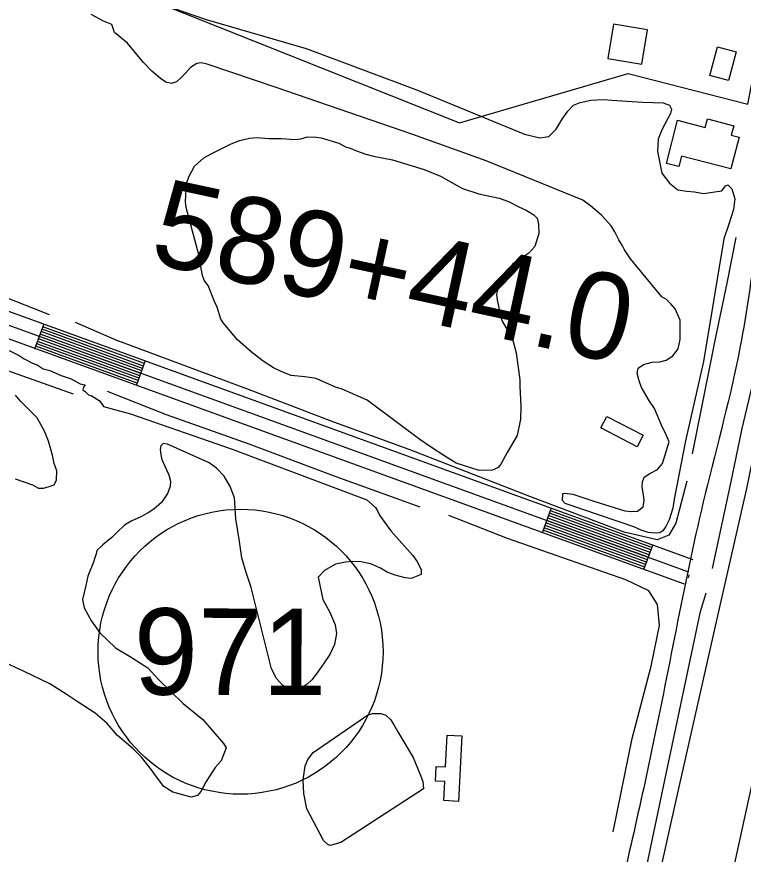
# Model space of a CAD drawing. Extents: x 3161564 to 3199464, y 849354 to 874788.
# Drawn here: x 3175202 to 3176044, y 870482 to 871452 of the extents above; entities that cross this region are included whole.
import ezdxf

# ---------------------------------------------------------------- set-up
doc = ezdxf.new("R2010")
doc.units = 0
for name, color, linetype in [('V-BLDG-OTLN', 7, 'Continuous'), ('V-LEVE-TOET', 7, 'Continuous'), ('V-ROAD-CNTR', 7, 'Continuous'), ('V-ROAD-IDEN', 7, 'Continuous'), ('V-SITE-VEGE', 7, 'Continuous'), ('V-SURV-IDEN', 7, 'Continuous'), ('V-SURV-LINE', 7, 'Continuous'), ('V-TOPO-SHOR', 7, 'Continuous')]:
    doc.layers.add(name, color=color, linetype=linetype)

msp = doc.modelspace()

# ---------------------------------------------------------------- linework, layer by layer
at = {"layer": 'V-BLDG-OTLN'}
for points in [[(3175886.83, 871403.4), (3175926.29, 871396.84), (3175932.85, 871436.3), (3175893.39, 871442.86)], [(3176026.57, 871377.88), (3176004.84, 871383.71), (3176013.71, 871416.78), (3176035.44, 871410.95)], [(3176029.37, 871275.43), (3175972.1, 871290.22), (3175968.99, 871278.16), (3175954.66, 871281.86), (3175967.55, 871331.8), (3175999.57, 871323.54), (3176002.08, 871333.25), (3176032.57, 871325.38), (3176029.78, 871314.53), (3176038.85, 871312.19)], [(3175927.8, 870967.13), (3175920.9, 870953.7), (3175878.57, 870975.46), (3175885.48, 870988.89)], [(3175713.82, 870543.08), (3175696.98, 870543.92), (3175698.1, 870566.1), (3175687.38, 870566.64), (3175688.24, 870583.62), (3175698.94, 870583.09), (3175700.79, 870619.84), (3175717.64, 870618.99)]]:
    msp.add_lwpolyline(points, close=True, dxfattribs=at)
at = {"layer": 'V-LEVE-TOET'}
msp.add_lwpolyline([(3175669.74, 869514.51), (3175708.2, 869561.86), (3175732.37, 869595.77), (3175748.33, 869623.04), (3175762.06, 869648.88), (3175775.26, 869685.57), (3175784.89, 869728.04), (3175832.2, 869934.29), (3175892.9, 870206.66), (3175926.27, 870366.31), (3175967.07, 870549.35), (3176018.86, 870778.5), (3176047.93, 870905.33), (3176080.45, 871065.53), (3176105.08, 871234.71), (3176159.34, 871580.12), (3176184.86, 871793.43), (3176216.77, 872030.74), (3176255.03, 872301.24), (3176314.08, 872686.62), (3176349.68, 872849.05), (3176380.96, 872978.37)], dxfattribs=at)
at = {"layer": 'V-ROAD-CNTR'}
for p, q in [((3175223.5, 871067.22), (3175233.73, 871095.43)), ((3175341.02, 871024.62), (3175351.24, 871052.82)), ((3175811.07, 870854.19), (3175821.3, 870882.39)), ((3175928.59, 870811.58), (3175938.81, 870839.79)), ((3175980.76, 870805.37), (3175979.96, 870801.73))]:
    msp.add_line(p, q, dxfattribs=at)
for points in [[(3175975.59, 870794.54), (3175143.47, 871096.24), (3175032.24, 871134.74), (3174921.57, 871175.58), (3174745.66, 871245.05), (3174571.09, 871317.8), (3174522.48, 871339.19), (3174474.33, 871361.8), (3174390.35, 871404.3), (3174308.03, 871450.04), (3174208.42, 871511.01)], [(3175985.82, 870822.74), (3175153.49, 871124.52), (3175042.34, 871162.99), (3174932.27, 871203.61), (3174756.94, 871272.85), (3174582.9, 871345.38), (3174534.9, 871366.51), (3174487.47, 871388.77), (3174404.42, 871430.8), (3174323.15, 871475.96)], [(3175980.71, 870808.64), (3175148.48, 871110.38)], [(3175348.18, 871044.36), (3175230.66, 871086.97)], [(3175349.2, 871047.18), (3175231.69, 871089.79)], [(3175350.22, 871050), (3175232.71, 871092.61)], [(3175345.11, 871035.9), (3175227.59, 871078.51)], [(3175346.13, 871038.72), (3175228.62, 871081.33)], [(3175347.15, 871041.54), (3175229.64, 871084.15)], [(3175342.04, 871027.44), (3175224.53, 871070.04)], [(3175343.06, 871030.26), (3175225.55, 871072.86)], [(3175344.09, 871033.08), (3175226.57, 871075.68)], [(3175935.75, 870831.33), (3175818.23, 870873.93)], [(3175936.77, 870834.15), (3175819.26, 870876.75)], [(3175937.79, 870836.97), (3175820.28, 870879.57)], [(3175932.68, 870822.86), (3175815.16, 870865.47)], [(3175933.7, 870825.68), (3175816.19, 870868.29)], [(3175934.72, 870828.5), (3175817.21, 870871.11)], [(3175929.61, 870814.4), (3175812.1, 870857.01)], [(3175930.63, 870817.22), (3175813.12, 870859.83)], [(3175931.66, 870820.04), (3175814.14, 870862.65)]]:
    msp.add_lwpolyline(points, dxfattribs=at)
msp.add_spline([(3176214.44, 872287.97), (3176116.81, 871676.86), (3176098.39, 871490.94), (3176090.67, 871415.87), (3176074.08, 871299.53), (3176058.21, 871187.52), (3176040.22, 871070.24), (3175999.55, 870899.04), (3175937.93, 870603.4), (3175884.93, 870365.76), (3175824.81, 870091.45), (3175789.97, 869942.79), (3175763.65, 869809.98), (3175731.11, 869705.44), (3175702.31, 869636.88), (3175675.03, 869598.47), (3175630.99, 869537.22), (3175579.38, 869482.41), (3175530.47, 869432.74), (3175484.14, 869377.74), (3175466.82, 869337.15), (3175448.87, 869288.95), (3175412.84, 869163.34), (3175354.17, 868894.67), (3175303.09, 868660.04), (3175288.27, 868568.95), (3175271.58, 868449.01), (3175249.11, 868331.03), (3175221.75, 868196.01), (3175175.82, 868026.92), (3175130.08, 867866.97), (3175087.93, 867676.37), (3175040.19, 867488.06), (3174985.36, 867232.29), (3174937.6, 866993.63), (3174859.65, 866658.78), (3174804.6, 866380.11), (3174764.51, 866230.53), (3174736.38, 866088.41)], degree=3, dxfattribs=at)
at = {"layer": 'V-ROAD-IDEN'}
msp.add_circle((3175461.56, 870716.37), 165, dxfattribs=at)
msp.add_circle((3175461.56, 870716.37), 165, dxfattribs=at)
at = {"layer": 'V-SITE-VEGE'}
for p, q in [((3175314.97, 871485.45), (3175421.69, 871448.5)), ((3175303.08, 871446.45), (3175288.72, 871454.2)), ((3175312.65, 871442.56), (3175303.08, 871446.45)), ((3175421.69, 871448.5), (3175537.68, 871414.86)), ((3175315.79, 871433.33), (3175312.65, 871442.56)), ((3175330.51, 871421.04), (3175315.79, 871433.33)), ((3175349.08, 871398.76), (3175330.51, 871421.04)), ((3175537.68, 871414.86), (3175666.52, 871366.44)), ((3175358.8, 871388.51), (3175349.08, 871398.76)), ((3175410.79, 871397.58), (3175403.72, 871392.97)), ((3175416.25, 871398.17), (3175410.79, 871397.58)), ((3175422.93, 871396.65), (3175416.25, 871398.17)), ((3175368.7, 871380.08), (3175358.8, 871388.51)), ((3175403.72, 871392.97), (3175397.73, 871386.24)), ((3175502.88, 871369.84), (3175422.93, 871396.65)), ((3175375.05, 871376.05), (3175368.7, 871380.08)), ((3175392.46, 871380.75), (3175387.34, 871376.24)), ((3175397.73, 871386.24), (3175392.46, 871380.75)), ((3175381.72, 871374.25), (3175375.05, 871376.05)), ((3175387.34, 871376.24), (3175381.72, 871374.25)), ((3175661.08, 871315.28), (3175502.88, 871369.84)), ((3175666.52, 871366.44), (3175790.44, 871315.75)), ((3175840.39, 871342.18), (3175847.23, 871349.17)), ((3175847.23, 871349.17), (3175854.83, 871352.24)), ((3175854.83, 871352.24), (3175867.31, 871354.93)), ((3175867.31, 871354.93), (3175881.43, 871355.78)), ((3175881.43, 871355.78), (3175897.2, 871354.64)), ((3175897.2, 871354.64), (3175926.78, 871352.82)), ((3175926.78, 871352.82), (3175950.92, 871351.8)), ((3175950.92, 871351.8), (3175958.28, 871349.29)), ((3175958.28, 871349.29), (3175960.71, 871344.77)), ((3175834.07, 871333.22), (3175840.39, 871342.18)), ((3175959.21, 871339.77), (3175949.79, 871321.51)), ((3175960.71, 871344.77), (3175959.21, 871339.77)), ((3175827, 871321.48), (3175834.07, 871333.22)), ((3175818.6, 871312.98), (3175827, 871321.48)), ((3175949.79, 871321.51), (3175944.95, 871309.73)), ((3175745.98, 871284.75), (3175661.08, 871315.28)), ((3175790.44, 871315.75), (3175808.23, 871311.36)), ((3175808.23, 871311.36), (3175818.6, 871312.98)), ((3175944.95, 871309.73), (3175944.27, 871295.64)), ((3175944.27, 871295.64), (3175949.52, 871270.67)), ((3175857.98, 871239.17), (3175745.98, 871284.75)), ((3175949.52, 871270.67), (3175958.23, 871259.05)), ((3175958.23, 871259.05), (3175968, 871251.04)), ((3176018.83, 871250.21), (3176023.13, 871256)), ((3176023.13, 871256), (3176025.8, 871256.92)), ((3176025.8, 871256.92), (3176030.33, 871252.51)), ((3176030.33, 871252.51), (3176033.88, 871240.85)), ((3175968, 871251.04), (3175978.17, 871249.59)), ((3175978.17, 871249.59), (3175987.09, 871248.86)), ((3175987.09, 871248.86), (3175997.68, 871247.12)), ((3175997.68, 871247.12), (3176018.83, 871250.21)), ((3175866.94, 871232.85), (3175857.98, 871239.17)), ((3175879.44, 871222), (3175866.94, 871232.85)), ((3176033.88, 871240.85), (3176032.25, 871228.58)), ((3176032.25, 871228.58), (3176027.03, 871211.64)), ((3175890.66, 871209.63), (3175879.44, 871222)), ((3175894.86, 871202.71), (3175890.66, 871209.63)), ((3176027.03, 871211.64), (3176021.25, 871194.29)), ((3175899.57, 871193.26), (3175894.86, 871202.71)), ((3176021.25, 871194.29), (3175997.46, 871052.41)), ((3175903.91, 871186.47), (3175899.57, 871193.26)), ((3175906.05, 871181.68), (3175903.91, 871186.47)), ((3175913.12, 871171.49), (3175906.05, 871181.68)), ((3175920.35, 871162.41), (3175913.12, 871171.49)), ((3175949.43, 871127.22), (3175920.35, 871162.41)), ((3175954.68, 871124.04), (3175949.43, 871127.22)), ((3175959.62, 871119.2), (3175954.68, 871124.04)), ((3175964.67, 871113.24), (3175959.62, 871119.2)), ((3175970.71, 871100.13), (3175964.67, 871113.24)), ((3175970.7, 871077.78), (3175970.71, 871100.13)), ((3175968.12, 871066.94), (3175970.7, 871077.78)), ((3175954.46, 871053.93), (3175962.24, 871059.09)), ((3175962.24, 871059.09), (3175968.12, 871066.94)), ((3175921.88, 871044.77), (3175928.25, 871048.98)), ((3175928.25, 871048.98), (3175938.21, 871051.58)), ((3175938.21, 871051.58), (3175947.02, 871052.11)), ((3175947.02, 871052.11), (3175954.46, 871053.93)), ((3175997.46, 871052.41), (3175976.71, 870960.47)), ((3175920.65, 871038.93), (3175921.88, 871044.77)), ((3175922.99, 871029.94), (3175920.65, 871038.93)), ((3175925.92, 871022.2), (3175922.99, 871029.94)), ((3175935.12, 871006.66), (3175925.92, 871022.2)), ((3175940.96, 870998.03), (3175935.12, 871006.66)), ((3175948.98, 870978.6), (3175940.96, 870998.03)), ((3175954.21, 870967.46), (3175948.98, 870978.6)), ((3175957.69, 870959.44), (3175954.21, 870967.46)), ((3175950.08, 870934.16), (3175957.69, 870959.44)), ((3175976.71, 870960.47), (3175963.69, 870892.97)), ((3175944.37, 870927.42), (3175950.08, 870934.16)), ((3175928.97, 870918.64), (3175935.48, 870922.84)), ((3175935.48, 870922.84), (3175944.37, 870927.42)), ((3175926.52, 870907.09), (3175927.05, 870912.95)), ((3175927.05, 870912.95), (3175928.97, 870918.64)), ((3175928.02, 870897.98), (3175926.52, 870907.09)), ((3175834.17, 870891.39), (3175834.74, 870899.48)), ((3175834.74, 870899.48), (3175836.71, 870900)), ((3175836.71, 870900), (3175846.18, 870898.7)), ((3175846.18, 870898.7), (3175857.85, 870895.13)), ((3175857.85, 870895.13), (3175870.61, 870890.83)), ((3175928.74, 870891.54), (3175928.02, 870897.98)), ((3175963.69, 870892.97), (3175961.95, 870882.67)), ((3175837.31, 870887.84), (3175834.17, 870891.39)), ((3175917.12, 870860.9), (3175837.31, 870887.84)), ((3175870.61, 870890.83), (3175906.44, 870879.68)), ((3175921.24, 870879.26), (3175927.62, 870884.3)), ((3175927.62, 870884.3), (3175928.74, 870891.54)), ((3175906.44, 870879.68), (3175914.24, 870878.55)), ((3175914.24, 870878.55), (3175921.24, 870879.26)), ((3175961.95, 870882.67), (3175957.93, 870869.2)), ((3175957.93, 870869.2), (3175953.87, 870861.45)), ((3175925.28, 870856.97), (3175917.12, 870860.9)), ((3175933.62, 870854.43), (3175925.28, 870856.97)), ((3175941.28, 870853.59), (3175933.62, 870854.43)), ((3175947.02, 870854.18), (3175941.28, 870853.59)), ((3175950.42, 870856.49), (3175947.02, 870854.18)), ((3175953.87, 870861.45), (3175950.42, 870856.49))]:
    msp.add_line(p, q, dxfattribs=at)
for points in [[(3175398.65, 871230.6), (3175397.99, 871237.46), (3175399.04, 871258.76), (3175402.19, 871267.09), (3175408.44, 871278.43), (3175419.23, 871288.18), (3175428.43, 871293.38), (3175450.66, 871304.5), (3175460.6, 871308.17), (3175472.06, 871311.06), (3175480.44, 871311.7), (3175494.13, 871310.76), (3175508.59, 871310.56), (3175524.56, 871309.58), (3175531.42, 871310.25), (3175539.06, 871312.43), (3175548.96, 871312.3), (3175555.03, 871311.45), (3175575.5, 871305.09), (3175583.06, 871301.18), (3175588.37, 871299.58), (3175595.94, 871296.43), (3175606.54, 871292.48), (3175615.64, 871290.08), (3175637.66, 871285.97), (3175674.05, 871274.82), (3175692.97, 871266.95), (3175718.66, 871252.9), (3175737.6, 871246.56), (3175761.14, 871241.67), (3175771.74, 871237.72), (3175783.83, 871231.47), (3175792.15, 871227.55), (3175801.21, 871222.1), (3175804.97, 871218.24), (3175806.4, 871211.37), (3175807.01, 871200.71), (3175802.24, 871185.55), (3175795.29, 871178.03), (3175776.85, 871165.34), (3175765.99, 871151.02), (3175762.86, 871144.21), (3175760.51, 871139.68), (3175758.93, 871135.13), (3175758.1, 871130.58), (3175758.77, 871123.72), (3175763.07, 871103.87), (3175764.53, 871099.28), (3175774.2, 871082.4), (3175777.15, 871075.51), (3175780.78, 871062.52), (3175784.92, 871031.26), (3175784.82, 871023.65), (3175786.03, 871000.79), (3175785.82, 870985.57), (3175781.76, 870966.6), (3175770.08, 870946.96), (3175763.04, 870933.36), (3175759.95, 870929.6), (3175755.35, 870927.37), (3175753.05, 870926.64), (3175737.82, 870926.09), (3175711.3, 870934.82), (3175696.95, 870943.39), (3175682.62, 870952.72), (3175669.04, 870962.04), (3175646.44, 870979.09), (3175608, 871007.78), (3175579.25, 871020.35), (3175571.67, 871022.73), (3175549.72, 871032.17), (3175546.69, 871032.97), (3175536.05, 871034.63), (3175520.09, 871036.37), (3175509.49, 871040.32), (3175499.66, 871045.02), (3175487.58, 871052.8), (3175474.03, 871063.64), (3175458.23, 871077.55), (3175441.75, 871096.81), (3175438.77, 871101.42), (3175434.38, 871115.18), (3175431.43, 871122.07), (3175424.07, 871140.44), (3175421.08, 871144.28), (3175419.59, 871146.59), (3175417.38, 871151.95), (3175414.56, 871168.73), (3175414.6, 871171.78)], [(3175577.7, 870495.53), (3175565.34, 870491.85), (3175562.71, 870493.16), (3175557.62, 870497.58), (3175538.49, 870534.41), (3175534.78, 870552.36), (3175534.25, 870568.15), (3175536.23, 870584.18), (3175539.44, 870591.38), (3175545.61, 870599.79), (3175608.44, 870642.72), (3175614.21, 870644.99), (3175623.99, 870644.94), (3175629.68, 870642.88), (3175635.58, 870637.46), (3175639.11, 870631.8), (3175643.83, 870623.47), (3175661.57, 870593.8), (3175669.72, 870574.23), (3175672.64, 870566.21), (3175673.31, 870557.68)]]:
    msp.add_lwpolyline(points, close=True, dxfattribs=at)
for points in [[(3175193.72, 871065.18), (3175205.21, 871059.37), (3175210.95, 871055.5), (3175220.52, 871050.65), (3175226.27, 871048.71), (3175232.96, 871043.88), (3175240.63, 871041.92), (3175254.03, 871036.1), (3175265.53, 871032.2), (3175276.06, 871026.39), (3175281.81, 871025.4), (3175279.88, 871022.53), (3175278.9, 871019.66), (3175281.77, 871017.72), (3175285.59, 871013.87), (3175288.47, 871012.89), (3175298.04, 871007.09), (3175301.85, 871002.27), (3175302.8, 871000.35), (3175334.05, 870991.72)], [(3175200.66, 870916.4), (3175220.78, 870909.59), (3175227.48, 870905.72), (3175233.24, 870905.68), (3175239.97, 870907.57), (3175245.73, 870909.46), (3175248.64, 870915.21), (3175248.69, 870925.76), (3175245.86, 870934.41), (3175243.98, 870944.02), (3175239.27, 870960.36), (3175234.52, 870971.89), (3175225.96, 870987.29), (3175206.87, 871006.58), (3175201.14, 871013.32)], [(3175334.05, 870991.72), (3175451.87, 870951.06), (3175607.75, 870892.22), (3175617.92, 870883.5), (3175620.63, 870878.7), (3175622.5, 870874.48), (3175635.57, 870856.49), (3175660.86, 870827.65), (3175665.49, 870821.13), (3175670.89, 870811.53), (3175670.78, 870805.95), (3175659.24, 870801.28), (3175652.27, 870801.83), (3175640.73, 870804.98), (3175631.44, 870808.65), (3175623.7, 870812.99), (3175613.18, 870817.8), (3175601.35, 870820.26), (3175591.31, 870821.01), (3175583.05, 870820.19), (3175571.41, 870817.76), (3175558.84, 870810.45), (3175551.43, 870802.63), (3175556.66, 870776.69), (3175564.76, 870762.01), (3175571.05, 870747.64), (3175572.82, 870737.41), (3175570.48, 870724.89), (3175564.81, 870713.12), (3175558.48, 870703.46), (3175550.3, 870691.89), (3175544.14, 870683.9), (3175538.87, 870678.83), (3175534.2, 870675.71), (3175528.15, 870673.03), (3175523.52, 870672), (3175517.96, 870673.37), (3175510.07, 870677.7), (3175503.1, 870685.38), (3175497.44, 870696.39), (3175493.68, 870711.82), (3175473.81, 870790.56), (3175468.14, 870808.27), (3175463.02, 870825.13), (3175460.3, 870843.9), (3175456.06, 870870.24), (3175454.42, 870894.58), (3175449.65, 870907.8), (3175442.75, 870919.67), (3175433.85, 870928.78), (3175425.16, 870935.09), (3175377.11, 870956.82), (3175371.95, 870957.34), (3175369.39, 870954.73), (3175368.47, 870950.42), (3175369.19, 870944.68), (3175370.62, 870938.92), (3175373.83, 870931.18), (3175378.67, 870921.31), (3175380.48, 870913.87), (3175379.94, 870907.59), (3175377.14, 870899.55), (3175370.23, 870889.2), (3175361.14, 870881.27), (3175354.5, 870877.07), (3175346.03, 870872.48), (3175335.03, 870867.38), (3175327.27, 870862.92), (3175318.17, 870854.57), (3175312.61, 870848.67), (3175302.01, 870840.09), (3175295.26, 870833.4), (3175294.28, 870829.57), (3175292.33, 870823.82), (3175291.35, 870819.99), (3175284.56, 870803.71), (3175282.59, 870793.16), (3175278.67, 870776.87), (3175280.54, 870767.26), (3175289.1, 870751.87), (3175298.63, 870738.38), (3175316.78, 870721.02), (3175333.04, 870711.34), (3175354.09, 870697.8), (3175366.5, 870684.31), (3175395.15, 870656.34), (3175418.09, 870637.99), (3175441.94, 870610.04), (3175444.8, 870605.23), (3175438.96, 870589.9), (3175432.21, 870582.26), (3175421.57, 870566), (3175415.76, 870554.51), (3175411.89, 870549.73), (3175404.21, 870547.85), (3175383.13, 870553.72), (3175372.6, 870560.48), (3175363.07, 870573), (3175358.3, 870579.75), (3175346.86, 870594.2), (3175337.31, 870603.84)], [(3175337.31, 870603.84), (3175319.15, 870619.28), (3175306.75, 870633.74), (3175293.37, 870645.32), (3175272.32, 870658.86), (3175260.85, 870666.6), (3175240.76, 870679.17), (3175210.12, 870693.72), (3175185.23, 870705.36)]]:
    msp.add_lwpolyline(points, dxfattribs=at)
at = {"layer": 'V-SURV-LINE'}
msp.add_lwpolyline([(3175864.42, 869697.01), (3176152.65, 871014.94)], dxfattribs=at)
at = {"layer": 'V-TOPO-SHOR'}
for p, q in [((3175094.18, 871163.76), (3175239.85, 871106.91)), ((3175270.04, 871098.03), (3175320.69, 871075.79)), ((3175268.27, 871014.54), (3175063.99, 871087.37))]:
    msp.add_line(p, q, dxfattribs=at)
for points in [[(3174800.2, 871693.11), (3175715.02, 871328.96), (3175910.42, 871385.8), (3176048.98, 871350.27), (3176084.51, 871535.02)], [(3175984.82, 870945.44), (3176011.9, 871080.7), (3176024.85, 871142.95), (3176035.3, 871196.06)], [(3175978.23, 870913.78), (3175965.37, 870865.29), (3175957.44, 870851.24), (3175943.77, 870845.73), (3175905.75, 870854.87), (3175796.5, 870896.14), (3175656.72, 870950.43), (3175569.77, 870982.24), (3175470.75, 871020.05), (3175320.69, 871075.79)], [(3176008.11, 870812.67), (3176029.11, 870911.53), (3176042.45, 870974.88), (3176059.44, 871046.43)], [(3175669.64, 870883.86), (3175572.33, 870919), (3175471.42, 870956.73), (3175375.85, 870990.71), (3175307.65, 871017.76)], [(3175893.11, 870507.65), (3175914.89, 870615.77), (3175937.09, 870699.51), (3175946.78, 870746.68), (3175944.48, 870770.97), (3175934.23, 870786.74), (3175907.72, 870799.56), (3175834.84, 870825.07), (3175770.82, 870847.39), (3175702.87, 870874.06)], [(3175603.63, 869456.84), (3175628.39, 869483.01), (3175656.34, 869512.44), (3175703.47, 869574.05), (3175722.4, 869602.91), (3175736.52, 869630.03), (3175755.96, 869676.17), (3175766.21, 869712.55), (3175793.84, 869831.5), (3175829.18, 869987.99), (3175873.69, 870192.47), (3175912.86, 870376.64), (3175952.9, 870567.78), (3175994.3, 870762.94), (3176000.78, 870784.69)]]:
    msp.add_lwpolyline(points, dxfattribs=at)

# ---------------------------------------------------------------- texts
at = {"layer": 'V-ROAD-IDEN'}
msp.add_text('971', height=100, rotation=359.84166, dxfattribs=at).set_placement((3175337.8, 870666.71))
at = {"layer": 'V-SURV-IDEN'}
msp.add_text('589+44.0', height=100, rotation=347.83083, dxfattribs=at).set_placement((3175354.27, 871167.23))

doc.saveas('drawing.dxf')
